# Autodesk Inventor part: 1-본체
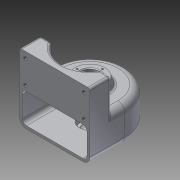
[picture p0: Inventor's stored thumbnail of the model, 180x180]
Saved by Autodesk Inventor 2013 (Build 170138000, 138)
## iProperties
Created: 2015-02
Part Number: 1-본체
Material: 알루미늄 6061
Document SubType Name: Modeling
Designer: Administrator
Density: 2.71 g/cm^3
Mass: 575.525 g
Surface Area: 706.56 cm^2
Volume: 212.371 cm^3
Author: Administrator
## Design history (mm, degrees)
sketch "스케치1"
  geometry: L1 (-50, 0)-(-50, -50); L2 (-50, -50)-(50, -50); L3 (50, -50)-(50, 0); A1 r 50 centre (0, 0) between (50, 0) and (-50, 0); 2 further points
  constraints: 6 end point, 2 point on circle, 2 tangent, 1 centre point, 1 coincident, 1 midpoint, 1 parallel, 1 perpendicular, 1 vertical, 1 vertical alignment
  dimensions: "d0" = 50 radius of A1; "d2" = 50 distance from line of L2 point (0, 0)
extrude "돌출1" new body sketch "스케치1" distance "d3" = 50; taper "d4" = 0 deg
feature "쉘1" dims "d18" = 4
sketch "스케치2"
  geometry: L1 (-50, 0)-(-50, -50) reference; L2 (-50, -50)-(50, -50) reference; L3 (50, -50)-(50, 0) reference; L4 (-34.641, -20)-(-50, -20); L5 (-50, -20)-(-50, -50); L6 (50, -50)-(-50, -50); L7 (50, -50)-(50, -20); L8 (50, -20)-(34.641, -20); A1 r 50 centre (0, 0) between (50, 0) and (-50, 0) reference; A2 r 40 centre (0, 0) between (-34.641, -20) and (34.641, -20); 2 further points
  constraints: 10 end point, 3 perpendicular, 2 midpoint, 2 point on circle, 2 point on line, 1 centre point, 1 coincident, 1 collinear, 1 horizontal alignment
  dimensions: "d5" = 40 radius of A2; "d7" = 30 distance between parallel lines of L2 L4
extrude "돌출2" join sketch "스케치2" distance "d8" = 45; taper "d9" = 0 deg
sketch "스케치3"
  geometry: C1 r 25 at (0, 0); A1 r 40 centre (0, 0) between (-34.641, -20) and (34.641, -20) reference
  constraints: 1 centre point, 1 coincident
  dimensions: "d10" = 50 diameter of C1
extrude "돌출3" join sketch "스케치3" distance "d12" = 10; taper "d13" = -20 deg
sketch "스케치4"
  geometry: C1 r 20 at (0, 0); A1 r 50 centre (0, 0) between (50, 0) and (-50, 0) reference
  constraints: 1 centre point, 1 coincident
  dimensions: "d14" = 40 diameter of C1
extrude "돌출4" join sketch "스케치4" distance "d16" = 9; taper "d17" = 0 deg
hole "구멍1" diameter "d21" = 20; stored, may be unused: countersink angle "d25" = 90 deg, drill point angle "d27" = 0 deg; dims "d19" = 10, "d20" = 10, "d22" = 6, "d23" = 28, "d24" = 10, "d26" = 14
sketch "스케치5"
  geometry: C1 r 14 at (0, 0); A1 r 46 centre (0, 0) between (46, 0) and (-46, 0) reference
  constraints: 1 centre point, 1 coincident
  dimensions: "d28" = 28 diameter of C1
extrude "돌출5" cut sketch "스케치5" distance "d30" = 8; taper "d31" = 0 deg
hole "구멍2" diameter "d34" = 20; stored, may be unused: countersink angle "d38" = 90 deg, drill point angle "d40" = 0 deg; dims "d32" = 10, "d33" = 10, "d35" = 6, "d36" = 28, "d37" = 10, "d39" = 2
sketch "스케치6"
  geometry: L1 (0, 95)-(100, 95) reference; L2 (0, 0)-(0, 95) reference; L3 (8.25, 86)-(91.75, 86); 7 further points
  constraints: 3 vertical alignment, 2 coincident, 2 end point, 2 midpoint, 1 horizontal alignment, 1 perpendicular
  dimensions: "d41" = 83.5 distance of L3.start L3.end; "d43" = 9 distance from line of L1 point (8.25, 86); "d44" = 33 distance of point (91.75, 86) point (91.75, 53)
hole "구멍3" sketch "스케치6" at (8.25, 86), (91.75, 86), (8.25, 53), (91.75, 53) diameter "d45" = 5.134; stored, may be unused: countersink angle "d49" = 90 deg, drill point angle "d51" = 118 deg; dims "d46" = 10, "d47" = 28, "d48" = 10, "d50" = 13
sketch "스케치7"
  geometry: C1 r 14 at (0, 0) reference; C2 r 21.36 at (0, 0) reference; A1 r 18 centre (0, 0) between (0, 18) and (-18, 0); 2 further points
  constraints: 4 point on circle, 2 horizontal alignment, 2 vertical alignment, 1 centre point, 1 coincident
  dimensions: "d52" = 36 diameter of A1
hole "구멍4" sketch "스케치7" at (0, 18), (-18, 0), (0, -18), (18, 0) diameter "d54" = 2.459; stored, may be unused: countersink angle "d58" = 90 deg, drill point angle "d60" = 118 deg; dims "d55" = 6, "d56" = 28, "d57" = 10, "d59" = 9
node "작업 평면1"
sketch "스케치8"
  geometry: L1 (-50, 0)-(50, 0) reference; 3 further points
  constraints: 1 midpoint, 1 vertical alignment, 1 other
  dimensions: "d61" = 25 distance from line of L1 point (0, 25)
feature "엠보싱1" sketch "스케치8" dims "d62" = 0.5, "d63" = 0
fillet "모깎기1" dims "d64" = 0.3
chamfer "모따기1" distance "d65" = 1; stored, may be unused: second distance "d66" = 2, angle "d67" = 45 deg
fillet "모깎기2" dims "d68" = 3
fillet "모깎기3" dims "d69" = 10, "d70" = 6
fillet "모깎기4" dims "d71" = 3
node "솔리드1"
